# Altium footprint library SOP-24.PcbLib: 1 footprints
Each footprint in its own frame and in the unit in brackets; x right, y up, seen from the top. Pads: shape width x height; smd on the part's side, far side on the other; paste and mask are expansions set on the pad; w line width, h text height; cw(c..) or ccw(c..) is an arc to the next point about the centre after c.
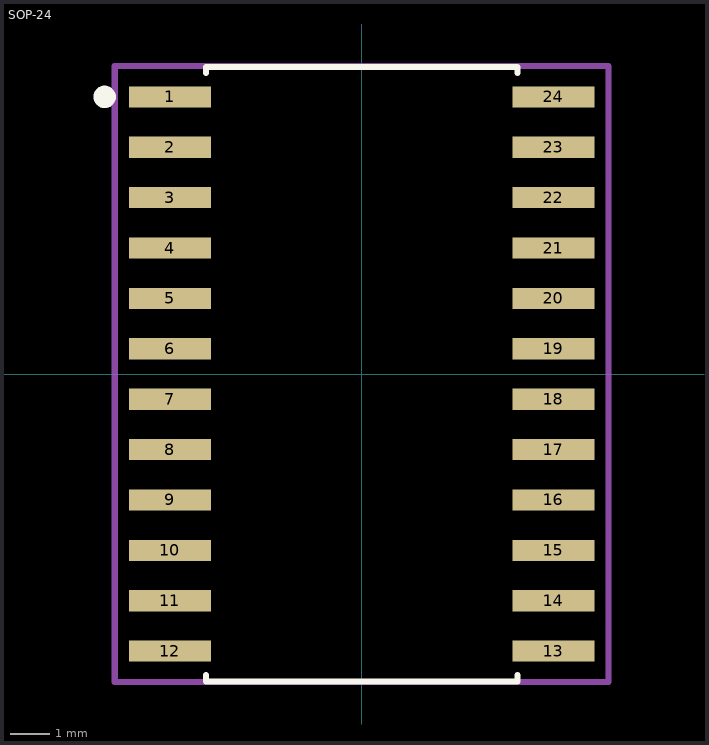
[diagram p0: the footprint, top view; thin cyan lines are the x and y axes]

## SOP-24 [mil]
pads (24):
  rect 81.5x21 smd: 1(-190.25,275) 2(-190.25,225) 3(-190.25,175) 4(-190.25,125) 5(-190.25,75) 6(-190.25,25) 7(-190.25,-25) 8(-190.25,-75) 9(-190.25,-125) 10(-190.25,-175) 11(-190.25,-225) 12(-190.25,-275) 13(190.25,-275) 14(190.25,-225) 15(190.25,-175) 16(190.25,-125) 17(190.25,-75) 18(190.25,-25) 19(190.25,25) 20(190.25,75) 21(190.25,125) 22(190.25,175) 23(190.25,225) 24(190.25,275)
Top Overlay:
  circle w11.81: c-255,275 r5.18
  lines w6: -154.5,-298.6 -154.5,-305.31 154.5,-305.31 154.5,-298.6 ; -154.5,298.6 -154.5,304.87 154.5,304.87 154.5,298.6
Mechanical 15:
  lines w6: -245,-305.5 -169.5,-305.5 169.5,-305.5 245,-305.5 245,305.5 169.5,305.5 -169.5,305.5 -245,305.5 -245,-305.5
3D body "SOP-24_ISI.step": height 104.09, standoff 0, extent -209.02,-307.01 209.02,307.01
